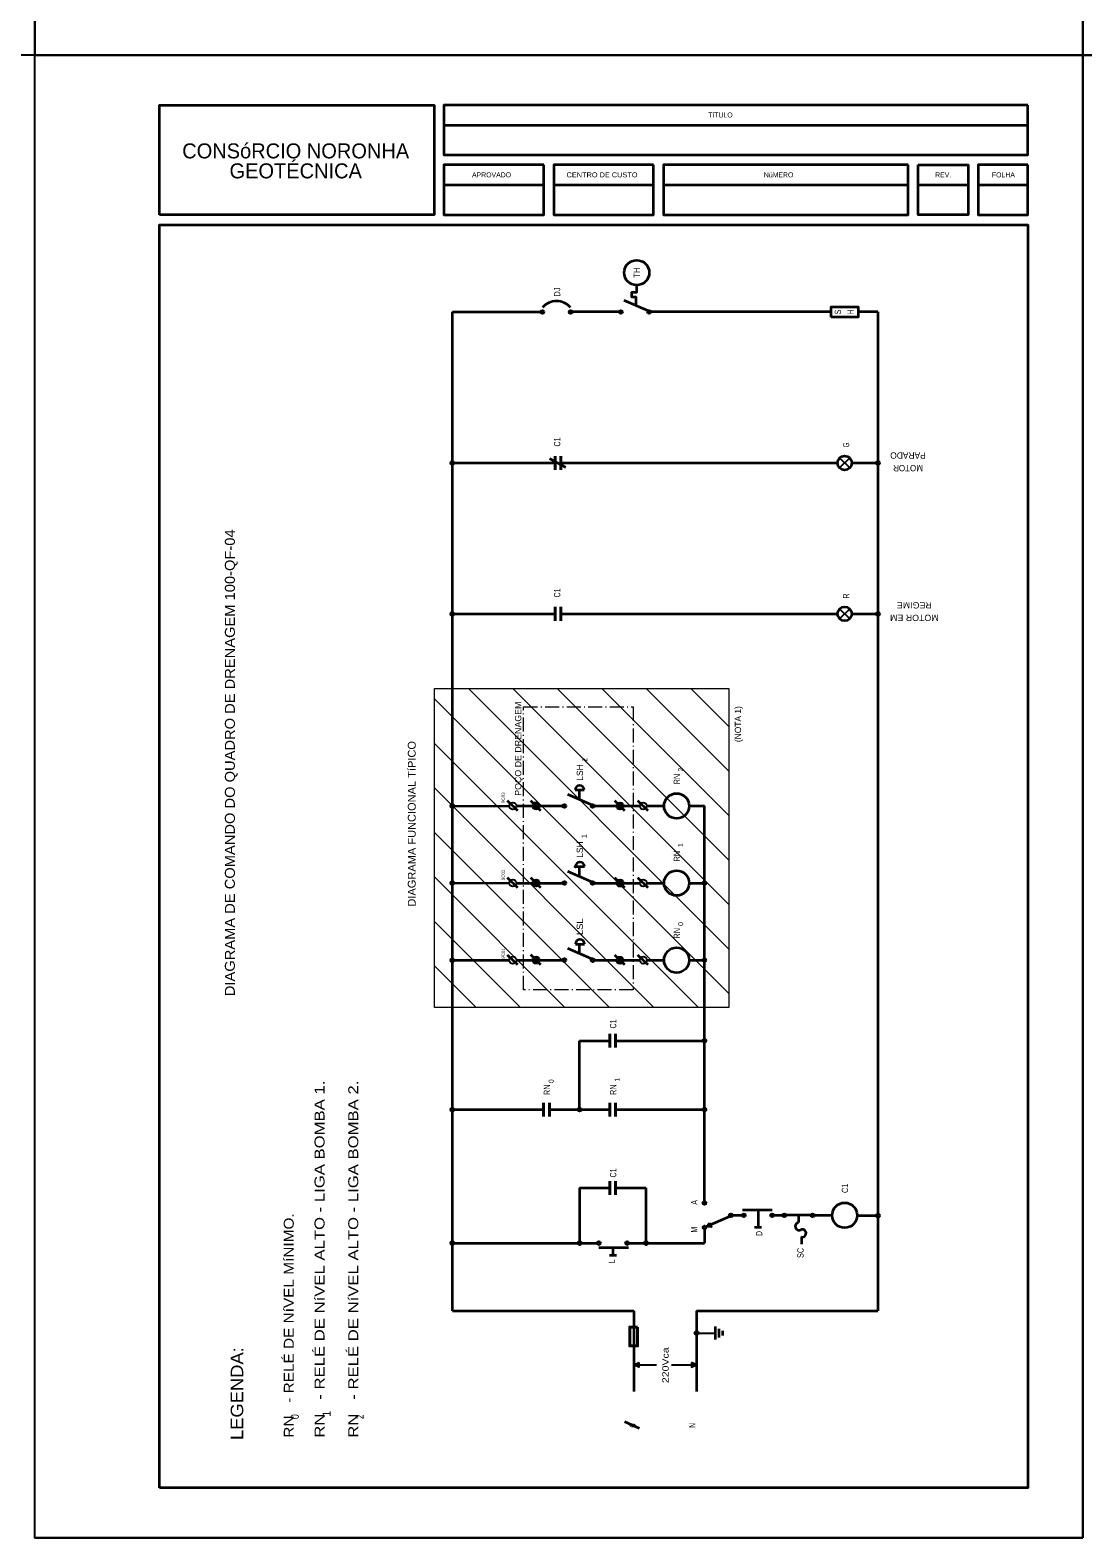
# Model space of a CAD drawing. Extents: x -4160 to -2690, y -474 to 714.
# Drawn here: x -3950.7 to -3739.8, y -473.5 to -171.5 of the extents above; entities that cross this region are included whole.
import ezdxf
from ezdxf.enums import TextEntityAlignment as Align

# ---------------------------------------------------------------- set-up
doc = ezdxf.new("R2010")
doc.units = 0
doc.header["$LTSCALE"] = 0.56
doc.header["$PDMODE"] = 32
doc.header["$PDSIZE"] = 0.28
doc.linetypes.add('DOT_DASHED', pattern=[7.7, 5, -1.2, 0.3, -1.2])
for name, color, linetype, lineweight in [('1', 7, 'Continuous', 25), ('4', 7, 'Continuous', 25), ('5', 7, 'Continuous', 35)]:
    doc.layers.add(name, color=color, linetype=linetype, lineweight=lineweight)

msp = doc.modelspace()

# ---------------------------------------------------------------- hatches: boundary and pattern name
at = {"layer": '1'}
for points in [[(-3866.0922, -257.8775, 1), (-3866.0922, -258.5274, 1)], [(-3780.8286, -257.8775, 1), (-3780.8286, -258.5274, 1)], [(-3866.0922, -288.1175, 1), (-3866.0922, -288.7674, 1)], [(-3780.8286, -288.1175, 1), (-3780.8286, -288.7674, 1)], [(-3866.0922, -326.6026, 1), (-3866.0922, -327.2524, 1)], [(-3849.3202, -327.6161, 1), (-3849.3202, -326.2001, 1)], [(-3832.4951, -327.6388, 1), (-3832.4951, -326.2227, 1)], [(-3866.0922, -342.045, 1), (-3866.0922, -342.6948, 1)], [(-3849.3202, -343.0585, 1), (-3849.3202, -341.6424, 1)], [(-3832.4951, -343.0812, 1), (-3832.4951, -341.6651, 1)], [(-3815.5658, -342.0379, 1), (-3815.5658, -342.6877, 1)], [(-3866.0922, -357.4873, 1), (-3866.0922, -358.1372, 1)], [(-3849.3202, -358.5009, 1), (-3849.3202, -357.0848, 1)], [(-3832.4951, -358.5235, 1), (-3832.4951, -357.1075, 1)], [(-3815.5658, -357.4803, 1), (-3815.5658, -358.1301, 1)], [(-3815.5658, -373.6273, 1), (-3815.5658, -374.2771, 1)], [(-3866.0922, -387.4229, 1), (-3866.0922, -388.0728, 1)], [(-3840.5928, -387.4229, 1), (-3840.5928, -388.0728, 1)], [(-3815.5658, -387.4229, 1), (-3815.5658, -388.0728, 1)], [(-3780.8286, -408.644, 1), (-3780.8286, -409.2938, 1)], [(-3866.0922, -414.1557, 1), (-3866.0922, -414.8055, 1)], [(-3840.5927, -414.1557, 1), (-3840.5927, -414.8055, 1)], [(-3827.3181, -414.1557, 1), (-3827.3181, -414.8055, 1)], [(-3817.1604, -432.1636, 1), (-3817.1604, -432.8135, 1)]]:
    msp.add_hatch(color=256, dxfattribs=at).paths.add_polyline_path(points)

# ---------------------------------------------------------------- linework, layer by layer
at = {"layer": '1', "lineweight": 35}
for p, q in [((-3826.8864, -227.7397), (-3831.6696, -225.6581)), ((-3866.0921, -428.0259), (-3866.0921, -227.9624)), ((-3866.0921, -227.9624), (-3848.3737, -227.9624)), ((-3832.6486, -227.9624), (-3842.0737, -227.9624)), ((-3790.1897, -227.9624), (-3826.3487, -227.9624)), ((-3780.8286, -227.9624), (-3784.7998, -227.9624)), ((-3780.8286, -227.9624), (-3780.8286, -428.0259)), ((-3866.0921, -258.2024), (-3845.5057, -258.2024)), ((-3846.6059, -257.3326), (-3843.4002, -259.0676)), ((-3844.3617, -258.2024), (-3788.9114, -258.2024)), ((-3786.0638, -258.2024), (-3780.8286, -258.2024)), ((-3866.0921, -288.4424), (-3845.5057, -288.4424)), ((-3844.3617, -288.4424), (-3788.9114, -288.4424)), ((-3786.0638, -288.4424), (-3780.8286, -288.4424)), ((-3855.1047, -325.8247), (-3853.0596, -327.8074)), ((-3850.4486, -325.8123), (-3848.4035, -327.7951)), ((-3838.2012, -326.6875), (-3842.9844, -324.6058)), ((-3841.5015, -323.7014), (-3841.5014, -323.7014)), ((-3841.5014, -323.7014), (-3839.6842, -323.7014)), ((-3840.5928, -325.6466), (-3840.5928, -323.7392)), ((-3833.6235, -325.835), (-3831.5784, -327.8178)), ((-3828.9674, -325.8227), (-3826.9223, -327.8054)), ((-3866.0921, -326.9275), (-3854.6843, -326.8998)), ((-3853.2683, -326.9101), (-3843.9635, -326.9101)), ((-3837.6635, -326.9101), (-3832.4573, -326.9101)), ((-3831.7872, -326.9205), (-3828.5471, -326.9205)), ((-3827.131, -326.9205), (-3823.6739, -326.9205)), ((-3818.6364, -326.9205), (-3815.5658, -326.9205)), ((-3815.5658, -406.1423), (-3815.5658, -326.9205)), ((-3850.4486, -341.2547), (-3848.4035, -343.2375)), ((-3838.2012, -342.1298), (-3842.9844, -340.0482)), ((-3841.4278, -339.0785), (-3839.6105, -339.0785)), ((-3840.5928, -341.089), (-3840.5928, -339.1816)), ((-3866.0921, -342.3699), (-3854.6843, -342.3422)), ((-3855.1047, -341.2671), (-3853.0596, -343.2498)), ((-3853.2683, -342.3525), (-3843.9635, -342.3525)), ((-3837.6635, -342.3525), (-3832.4573, -342.3525)), ((-3833.6235, -341.2774), (-3831.5784, -343.2602)), ((-3831.7872, -342.3629), (-3828.5471, -342.3629)), ((-3828.9674, -341.265), (-3826.9223, -343.2478)), ((-3827.131, -342.3629), (-3823.6739, -342.3629)), ((-3818.6364, -342.3629), (-3815.5658, -342.3629)), ((-3838.2012, -357.5721), (-3842.9844, -355.4905)), ((-3841.4278, -354.6024), (-3841.4278, -354.6025)), ((-3841.4278, -354.6025), (-3839.6105, -354.6025)), ((-3840.5928, -356.5314), (-3840.5928, -354.624)), ((-3866.0921, -357.8123), (-3854.6843, -357.7845)), ((-3855.1047, -356.7095), (-3853.0596, -358.6922)), ((-3853.2683, -357.7949), (-3843.9635, -357.7949)), ((-3850.4486, -356.6971), (-3848.4035, -358.6799)), ((-3837.6635, -357.7949), (-3832.4573, -357.7949)), ((-3833.6235, -356.7198), (-3831.5784, -358.7025)), ((-3831.7872, -357.8052), (-3828.5471, -357.8052)), ((-3828.9674, -356.7074), (-3826.9223, -358.6902)), ((-3827.131, -357.8052), (-3823.6739, -357.8052)), ((-3818.6364, -357.8052), (-3815.5658, -357.8052)), ((-3840.5928, -387.7479), (-3840.5928, -373.9522)), ((-3840.5928, -373.9522), (-3834.5275, -373.9522)), ((-3833.3835, -373.9522), (-3815.5658, -373.9522)), ((-3866.0921, -387.7479), (-3847.8022, -387.7479)), ((-3846.6581, -387.7479), (-3834.5275, -387.7479)), ((-3833.3835, -387.7479), (-3815.5658, -387.7479)), ((-3840.5927, -403.4381), (-3834.5275, -403.4381)), ((-3840.5927, -403.4381), (-3840.5927, -414.4806)), ((-3833.3835, -403.4381), (-3827.3182, -403.4381)), ((-3827.3182, -403.4381), (-3827.3182, -414.4806)), ((-3810.5035, -409.1301), (-3815.2866, -411.2117)), ((-3809.9657, -408.9073), (-3808.0059, -408.9073)), ((-3801.9883, -407.9082), (-3807.9449, -407.9082)), ((-3804.8343, -407.9082), (-3804.8343, -411.3476)), ((-3801.706, -408.9073), (-3799.8942, -408.9073)), ((-3794.2243, -408.9073), (-3799.2642, -408.9073)), ((-3796.7226, -408.9073), (-3796.7226, -410.3587)), ((-3793.5943, -408.9073), (-3790.0063, -408.9073)), ((-3784.9696, -408.9689), (-3780.8286, -408.9689)), ((-3815.5658, -411.6724), (-3815.5658, -414.4806)), ((-3804.1228, -411.3476), (-3805.5458, -411.3476)), ((-3796.153, -413.2532), (-3796.153, -414.7046)), ((-3866.0921, -414.4806), (-3837.0469, -414.4806)), ((-3836.7645, -415.3416), (-3830.8079, -415.3416)), ((-3833.9185, -415.3416), (-3833.9185, -416.9208)), ((-3830.747, -414.4806), (-3815.5658, -414.4806)), ((-3834.6299, -416.9208), (-3833.2071, -416.9208)), ((-3866.0921, -428.0259), (-3829.7604, -428.0259)), ((-3829.7604, -428.0259), (-3829.7604, -444.2392)), ((-3817.1604, -428.0259), (-3817.1604, -444.2392)), ((-3817.1604, -428.0259), (-3780.8286, -428.0259)), ((-3813.3506, -433.7868), (-3813.3506, -431.1902)), ((-3812.6568, -433.3899), (-3812.6568, -431.6345)), ((-3811.9265, -432.9876), (-3811.9265, -432.0367))]:
    msp.add_line(p, q, dxfattribs=at)
at = {"layer": '1', "lineweight": 40}
for p, q in [((-3845.5057, -259.58), (-3845.5057, -256.825)), ((-3844.3617, -259.58), (-3844.3617, -256.825)), ((-3845.5057, -289.82), (-3845.5057, -287.065)), ((-3844.3617, -289.82), (-3844.3617, -287.065)), ((-3834.5275, -372.5747), (-3834.5275, -375.3298)), ((-3833.3835, -372.5747), (-3833.3835, -375.3298)), ((-3847.8022, -389.1254), (-3847.8022, -386.3702)), ((-3846.6581, -389.1254), (-3846.6581, -386.3702)), ((-3834.5275, -389.1254), (-3834.5275, -386.3702)), ((-3833.3835, -389.1254), (-3833.3835, -386.3702)), ((-3834.5275, -404.8157), (-3834.5275, -402.0606)), ((-3833.3835, -404.8157), (-3833.3835, -402.0606))]:
    msp.add_line(p, q, dxfattribs=at)
at = {"layer": '1'}
for p, q in [((-3788.4944, -257.1956), (-3786.4808, -259.2092)), ((-3788.4944, -259.2092), (-3786.4809, -257.1957)), ((-3788.4944, -287.4356), (-3786.4808, -289.4492)), ((-3788.4944, -289.4492), (-3786.4809, -287.4357)), ((-3817.1604, -432.4886), (-3813.3506, -432.4886)), ((-3829.7604, -438.8752), (-3825.1792, -438.8752)), ((-3822.1755, -438.8752), (-3817.1604, -438.8752))]:
    msp.add_line(p, q, dxfattribs=at)
at = {"layer": '1', "lineweight": 13}
for p, q in [((-3810.6899, -355.5732), (-3862.8817, -303.3814)), ((-3810.6899, -346.6636), (-3853.9721, -303.3814)), ((-3810.6899, -337.754), (-3845.0626, -303.3814)), ((-3810.6899, -328.8446), (-3836.1531, -303.3814)), ((-3810.6899, -319.935), (-3827.2435, -303.3814)), ((-3810.6899, -311.0254), (-3818.334, -303.3814)), ((-3810.6899, -364.4827), (-3869.6896, -305.483)), ((-3816.7973, -367.2848), (-3869.6896, -314.3926)), ((-3825.707, -367.2848), (-3869.6896, -323.3021)), ((-3834.6165, -367.2848), (-3869.6896, -332.2117)), ((-3843.526, -367.2848), (-3869.6896, -341.1211)), ((-3852.4356, -367.2848), (-3869.6896, -350.0308)), ((-3861.3451, -367.2848), (-3869.6896, -358.9402))]:
    msp.add_line(p, q, dxfattribs=at)
at = {"layer": '1', "lineweight": 35}
msp.add_lwpolyline([(-3829.2779, -226.6989), (-3829.2779, -224.9976), (-3830.1418, -224.9976), (-3830.1418, -224.0092), (-3829.1525, -224.0092), (-3829.1525, -222.6137)], dxfattribs=at)
msp.add_lwpolyline([(-3790.1897, -229.0097), (-3790.1897, -226.9152), (-3784.7998, -226.9152), (-3784.7998, -229.0097)], close=True, dxfattribs=at)
at = {"layer": '1', "lineweight": 13}
msp.add_lwpolyline([(-3869.6896, -367.2848), (-3869.6896, -303.3814), (-3810.6899, -303.3814), (-3810.6899, -367.2848)], close=True, dxfattribs=at)
at = {"layer": '1', "linetype": 'DOT_DASHED', "lineweight": 13}
msp.add_lwpolyline([(-3851.8016, -363.7722), (-3851.8016, -307.0677), (-3829.8827, -307.0677), (-3829.8827, -363.7722)], close=True, dxfattribs=at)
at = {"layer": '1'}
for points in [[(-3814.5519, -410.391), (-3814.1682, -411.2626), (-3815.2775, -411.2305)], [(-3828.7581, -438.3991), (-3828.7581, -439.3514), (-3829.7604, -438.8752)], [(-3818.1627, -438.3991), (-3818.1627, -439.3514), (-3817.1604, -438.8752)]]:
    msp.add_lwpolyline(points, close=True, dxfattribs=at)
at = {"layer": '1', "lineweight": 40}
msp.add_lwpolyline([(-3828.9668, -431.2947), (-3828.9668, -435.0594), (-3830.554, -435.0594), (-3830.554, -431.2947)], close=True, dxfattribs=at)
at = {"layer": '1', "lineweight": 35}
for centre, radius in [((-3829.1526, -220.0949), 2.5187), ((-3848.0586, -227.9625), 0.315), ((-3842.3887, -227.9625), 0.315), ((-3832.3336, -227.9625), 0.315), ((-3826.6637, -227.9625), 0.315), ((-3866.0922, -258.2025), 0.3249), ((-3787.4876, -258.2024), 1.4238), ((-3780.8286, -258.2025), 0.3249), ((-3866.0922, -288.4425), 0.3249), ((-3787.4876, -288.4424), 1.4238), ((-3780.8286, -288.4425), 0.3249), ((-3821.1552, -326.9205), 2.5187), ((-3866.0922, -326.9275), 0.3249), ((-3843.6485, -326.9101), 0.315), ((-3837.9785, -326.9101), 0.315), ((-3821.1552, -342.3628), 2.5187), ((-3866.0922, -342.3699), 0.3249), ((-3843.6485, -342.3525), 0.315), ((-3837.9785, -342.3525), 0.315), ((-3815.5658, -342.3628), 0.3249), ((-3821.1552, -357.8052), 2.5187), ((-3866.0922, -357.8123), 0.3249), ((-3843.6485, -357.7949), 0.315), ((-3837.9785, -357.7949), 0.315), ((-3815.5658, -357.8052), 0.3249), ((-3815.5658, -373.9522), 0.3249), ((-3866.0922, -387.7478), 0.3249), ((-3840.5928, -387.7478), 0.3249), ((-3815.5658, -387.7478), 0.3249), ((-3815.5658, -406.4572), 0.315), ((-3787.4876, -408.9073), 2.5187), ((-3810.2807, -408.9073), 0.315), ((-3807.6908, -408.9073), 0.315), ((-3802.0209, -408.9073), 0.315), ((-3799.5791, -408.9073), 0.315), ((-3793.9092, -408.9073), 0.315), ((-3780.8286, -408.9689), 0.3249), ((-3815.5658, -411.3574), 0.315), ((-3866.0922, -414.4806), 0.3249), ((-3840.5927, -414.4806), 0.3249), ((-3836.7319, -414.4806), 0.315), ((-3831.0619, -414.4806), 0.315), ((-3827.3181, -414.4806), 0.3249), ((-3817.1604, -432.4886), 0.3249)]:
    msp.add_circle(centre, radius, dxfattribs=at)
at = {"layer": '1'}
for centre in [(-3853.9763, -326.9204), (-3849.3202, -326.9081), (-3832.4951, -326.9308), (-3827.839, -326.9184), (-3853.9763, -342.3628), (-3849.3202, -342.3505), (-3832.4951, -342.3731), (-3827.839, -342.3608), (-3853.9763, -357.8052), (-3849.3202, -357.7928), (-3832.4951, -357.8155), (-3827.839, -357.8032)]:
    msp.add_circle(centre, 0.708, dxfattribs=at)
at = {"layer": '1', "lineweight": 35}
for centre, radius, start, end in [((-3845.2236, -229.5012), 3.7184, 40.32226, 139.67774), ((-3840.5928, -323.7014), 0.9086, 0, 180), ((-3840.5192, -339.0785), 0.9086, 0, 180), ((-3840.5192, -354.6024), 0.9086, 0, 180), ((-3796.608, -411.1158), 0.7658, 98.60196, 294.20772), ((-3795.9801, -412.5126), 0.7658, 255.28226, 114.20772)]:
    msp.add_arc(centre, radius, start, end, dxfattribs=at)
at = {"layer": '1'}
msp.add_point((-3841.4278, -339.0785), dxfattribs=at)
at = {"layer": '4', "lineweight": 35}
msp.add_line((-3828.5939, -451.632), (-3831.5155, -450.2814), dxfattribs=at)
at = {"layer": '5', "lineweight": 25}
for p, q in [((-3739.7642, -176.52), (-3739.7642, 120.48)), ((-3949.7642, -176.52), (-4159.7642, -176.52)), ((-3949.7642, -473.52), (-3739.7642, -473.52))]:
    msp.add_line(p, q, dxfattribs=at)
at = {"layer": '5'}
for p, q in [((-3867.7642, -190.52), (-3750.7642, -190.52)), ((-3867.7642, -202.52), (-3847.7642, -202.52)), ((-3845.7642, -202.52), (-3825.7642, -202.52)), ((-3823.7642, -202.52), (-3774.7642, -202.52)), ((-3772.7642, -202.52), (-3762.7642, -202.52)), ((-3760.7642, -202.52), (-3750.7642, -202.52))]:
    msp.add_line(p, q, dxfattribs=at)
at = {"layer": '5', "lineweight": 25}
for points in [[(-4159.7642, 120.48), (-3949.7642, 120.48), (-3949.7642, -176.52)], [(-3739.7642, -473.52), (-3949.7642, -473.52), (-3949.7642, -176.52), (-3739.7642, -176.52)], [(-3739.7642, -473.52), (-3739.7642, -176.52), (-3739.7642, -473.52)], [(-3739.7642, -176.52), (-3529.7642, -176.52), (-3739.7642, -176.52)]]:
    msp.add_lwpolyline(points, dxfattribs=at)
msp.add_lwpolyline([(-3739.7642, -176.52), (-3949.7642, -176.52), (-3949.7642, 120.48), (-3739.7642, 120.48)], close=True, dxfattribs=at)
at = {"layer": '5'}
for points in [[(-3924.7642, -208.52), (-3924.7642, -186.52), (-3869.7642, -186.52), (-3869.7642, -208.52)], [(-3750.7642, -186.52), (-3867.7642, -186.52), (-3867.7642, -196.52), (-3750.7642, -196.52)], [(-3847.7642, -198.52), (-3867.7642, -198.52), (-3867.7642, -208.52), (-3847.7642, -208.52)], [(-3825.7642, -198.52), (-3845.7642, -198.52), (-3845.7642, -208.52), (-3825.7642, -208.52)], [(-3774.7642, -198.52), (-3823.7642, -198.52), (-3823.7642, -208.52), (-3774.7642, -208.52)], [(-3772.7642, -198.52), (-3762.7642, -198.52), (-3762.7642, -208.52), (-3772.7642, -208.52)], [(-3750.7642, -198.52), (-3760.7642, -198.52), (-3760.7642, -208.52), (-3750.7642, -208.52)], [(-3924.7642, -463.52), (-3924.7642, -210.52), (-3750.7642, -210.52), (-3750.7642, -463.52)]]:
    msp.add_lwpolyline(points, close=True, dxfattribs=at)

# ---------------------------------------------------------------- texts
at = {"layer": '1'}
for s, height, width, p in [('TH', 1.26, 0.9, (-3828.5225, -220.0949)), ('DJ', 1.26, 0.9, (-3844.4734, -223.9874)), ('S', 1.26, 0.7, (-3788.2244, -227.9792)), ('H', 1.26, 0.6, (-3785.7044, -227.9793)), ('C1', 1.26, 0.75, (-3844.4734, -254.0082)), ('G', 1.26, 0.6, (-3786.5809, -254.6194)), ('C1', 1.26, 0.75, (-3844.4734, -284.2482)), ('R', 1.26, 0.65, (-3786.5809, -284.8578)), ('2', 1.008, 0.75, (-3839.0639, -317.6702)), ('2', 1.008, 0.75, (-3819.8443, -319.6429)), ('9C03', 0.63, 1.05, (-3855.6027, -325.2663)), ('9C02', 0.63, 1.05, (-3855.6027, -340.7257)), ('LSL', 1.26, 1.1, (-3839.9289, -351.1028)), ('0', 1.008, 0.85, (-3819.8443, -350.5679)), ('9C01', 0.63, 0.9, (-3855.6027, -356.4712)), ('0', 1.008, 0.85, (-3845.7835, -382.0457)), ('A', 1.26, 0.75, (-3816.9851, -406.3252)), ('M', 1.26, 0.65, (-3816.9851, -411.798)), ('D', 1.26, 0.65, (-3803.9996, -412.5555)), ('SC', 1.26, 0.85, (-3795.7167, -416.4512)), ('L', 1.26, 0.8, (-3833.4932, -418.1288)), ('LEGENDA:', 2.5, 1.1, (-3907.994, -444.6324)), ('220Vca', 1.26, 1.25, (-3822.758, -438.9443)), ('0', 1.6, 0.85, (-3896.8571, -449.2548)), ('2', 1.6, 0.75, (-3883.8657, -449.2548)), ('0', 1.26, 0.9, (-3829.3301, -451.0146))]:
    msp.add_text(s, height=height, rotation=90, dxfattribs=dict(at, width=width)).set_placement(p, align=Align.CENTER)
at = {"layer": '1', "width": 1.1}
msp.add_text('DIAGRAMA DE COMANDO DO QUADRO DE DRENAGEM 100-QF-04', height=2, rotation=90, dxfattribs=at).set_placement((-3909.6617, -365.0231))
at = {"layer": '1'}
msp.add_text('(NOTA 1)', height=1.26, rotation=90, dxfattribs=at).set_placement((-3808.2372, -314.1348))
for s, height, p in [('LSH', 1.26, (-3839.9289, -320.218)), ('LSH', 1.26, (-3839.9289, -335.6604)), ('1', 1.008, (-3839.18, -332.9577)), ('1', 1.008, (-3819.8443, -334.7564)), ('1', 1.008, (-3832.5418, -381.7613)), ('1', 1.6, (-3890.5008, -448.6546))]:
    msp.add_text(s, height=height, rotation=90, dxfattribs=at).set_placement(p, align=Align.CENTER)
at = {"layer": '4'}
msp.add_text('PARADO', height=1.26, rotation=180, dxfattribs=at).set_placement((-3774.797, -256.0972), align=Align.CENTER)
for s, height, rotation, width, p in [('MOTOR', 1.26, 180, 0.95, (-3774.7969, -258.6172)), ('REGIME', 1.26, 180, 1.05, (-3773.5241, -286.0997)), ('MOTOR EM', 1.26, 180, 1.05, (-3773.524, -288.6197)), ('DIAGRAMA FUNCIONAL TíPICO', 1.575, 90, 1.05, (-3873.4331, -330.4956)), ('RN', 1.26, 90, 0.85, (-3820.4703, -321.5329)), ('RN', 1.26, 90, 0.85, (-3820.4703, -336.9753)), ('RN', 1.26, 90, 0.85, (-3820.4703, -352.4176)), ('C1', 1.26, 90, 0.75, (-3833.2567, -370.583)), ('RN', 1.26, 90, 0.85, (-3846.5136, -383.7651)), ('RN', 1.26, 90, 0.85, (-3833.2567, -383.7651)), ('C1', 1.26, 90, 0.75, (-3833.2567, -400.4294)), ('C1', 1.26, 90, 0.75, (-3786.8027, -403.5198)), ('N', 1.26, 90, 0.65, (-3817.419, -451.0066))]:
    msp.add_text(s, height=height, rotation=rotation, dxfattribs=dict(at, width=width)).set_placement(p, align=Align.CENTER)
for s, height, width, p in [('POÇO DE DRENAGEM', 1.26, 1.05, (-3852.288, -324.887)), ('RN   - RELÉ DE NíVEL ALTO - LIGA BOMBA 1.', 2, 1.25, (-3891.701, -453.4624)), ('RN   - RELÉ DE NíVEL ALTO - LIGA BOMBA 2.', 2, 1.25, (-3884.9435, -453.4624)), ('RN   - RELÉ DE NíVEL MíNIMO.', 2, 1.15, (-3897.8622, -453.4624))]:
    msp.add_text(s, height=height, rotation=90, dxfattribs=dict(at, width=width)).set_placement(p)
at = {"layer": '5'}
for s, height, p in [('TíTULO', 1, (-3812.3847, -189.009)), ('CONSóRCIO NORONHA', 3, (-3897.4749, -197.2039)), ('GEOTÉCNICA', 3, (-3897.475, -201.2039)), ('APROVADO', 1, (-3858.2387, -201.0027)), ('REV.', 1, (-3767.7444, -201.0077)), ('FOLHA', 1, (-3755.681, -201.0077))]:
    msp.add_text(s, height=height, dxfattribs=at).set_placement(p, align=Align.CENTER)
for s, width, p in [('CENTRO DE CUSTO', 1.1, (-3836.0934, -201.0027)), ('NúMERO', 0.95, (-3800.7228, -201.0077))]:
    msp.add_text(s, height=1, dxfattribs=dict(at, width=width)).set_placement(p, align=Align.CENTER)

doc.saveas('drawing.dxf')
